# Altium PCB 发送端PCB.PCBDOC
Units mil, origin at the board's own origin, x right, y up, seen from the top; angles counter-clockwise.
Board outline 1459.66 x 397.67 mil, 4 copper layers (Top Layer, Mid-Layer 1, Mid-Layer 2, Bottom Layer); 48 components, 37 nets, 169 pads, 76 vias.
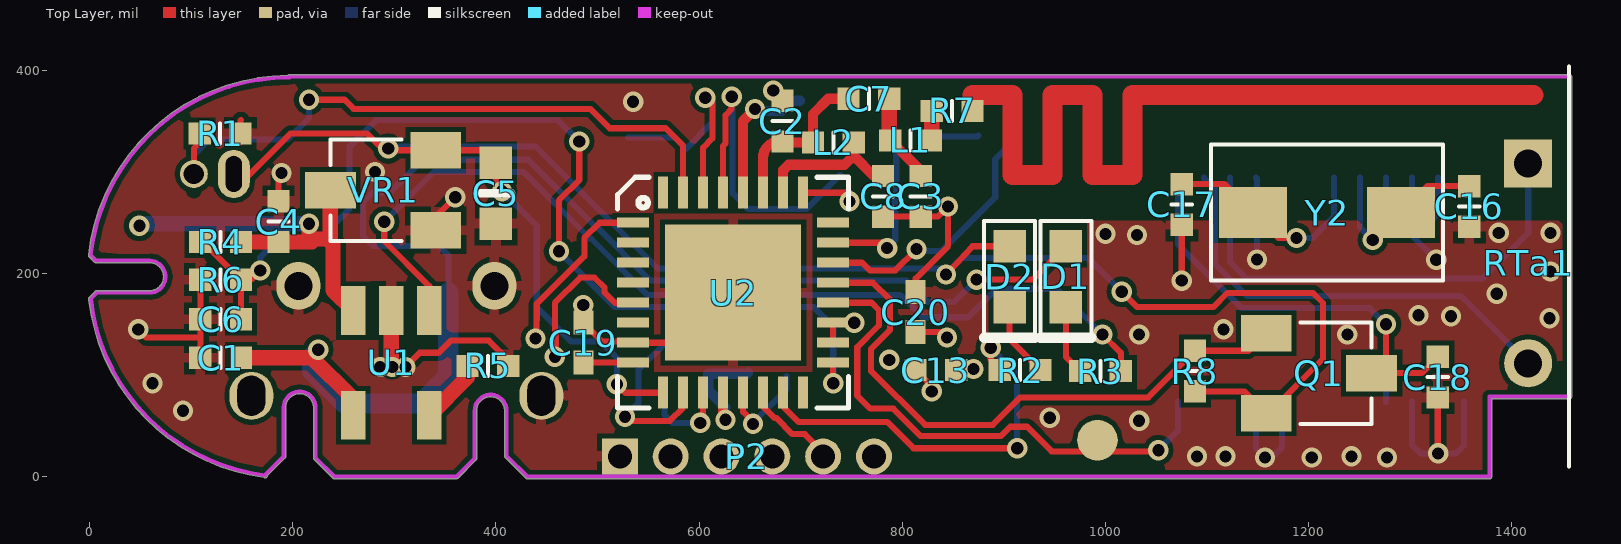
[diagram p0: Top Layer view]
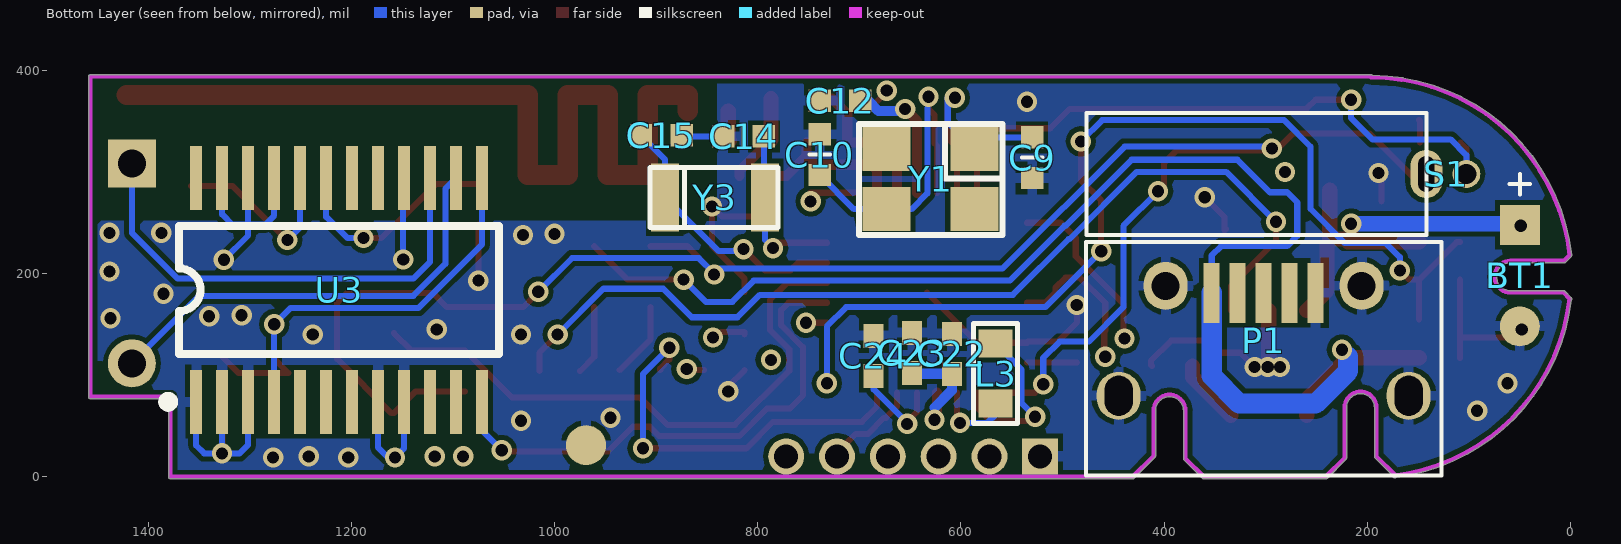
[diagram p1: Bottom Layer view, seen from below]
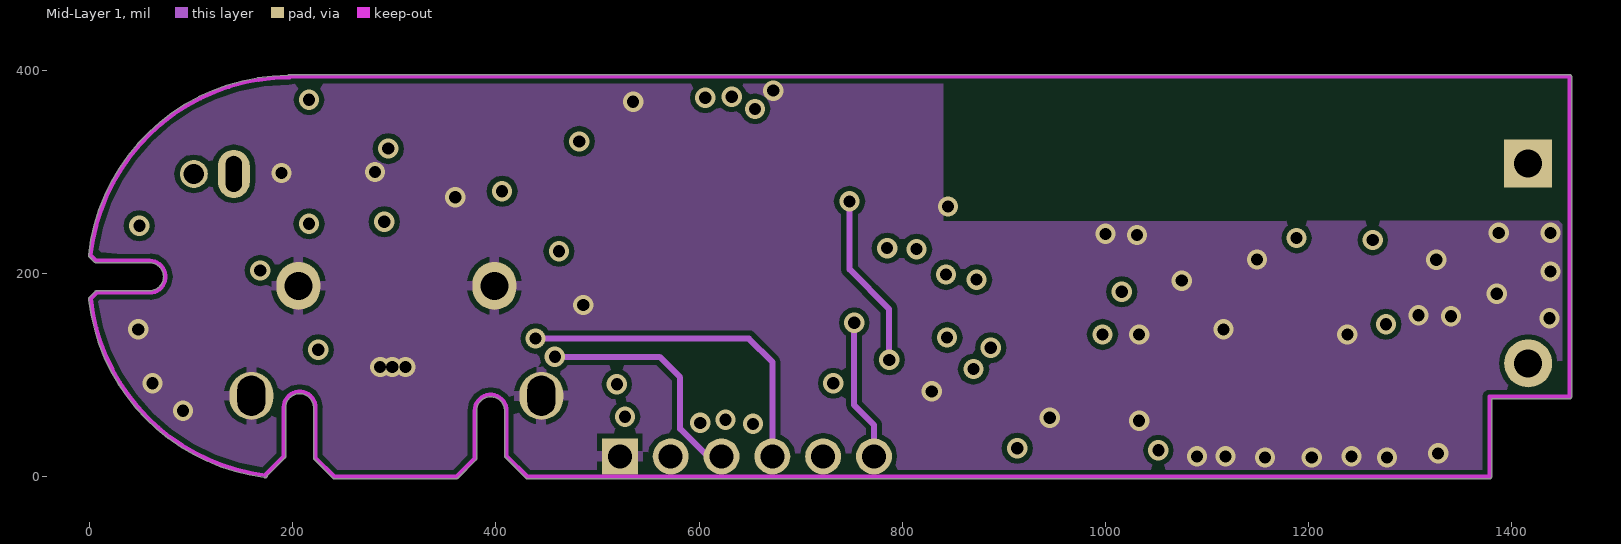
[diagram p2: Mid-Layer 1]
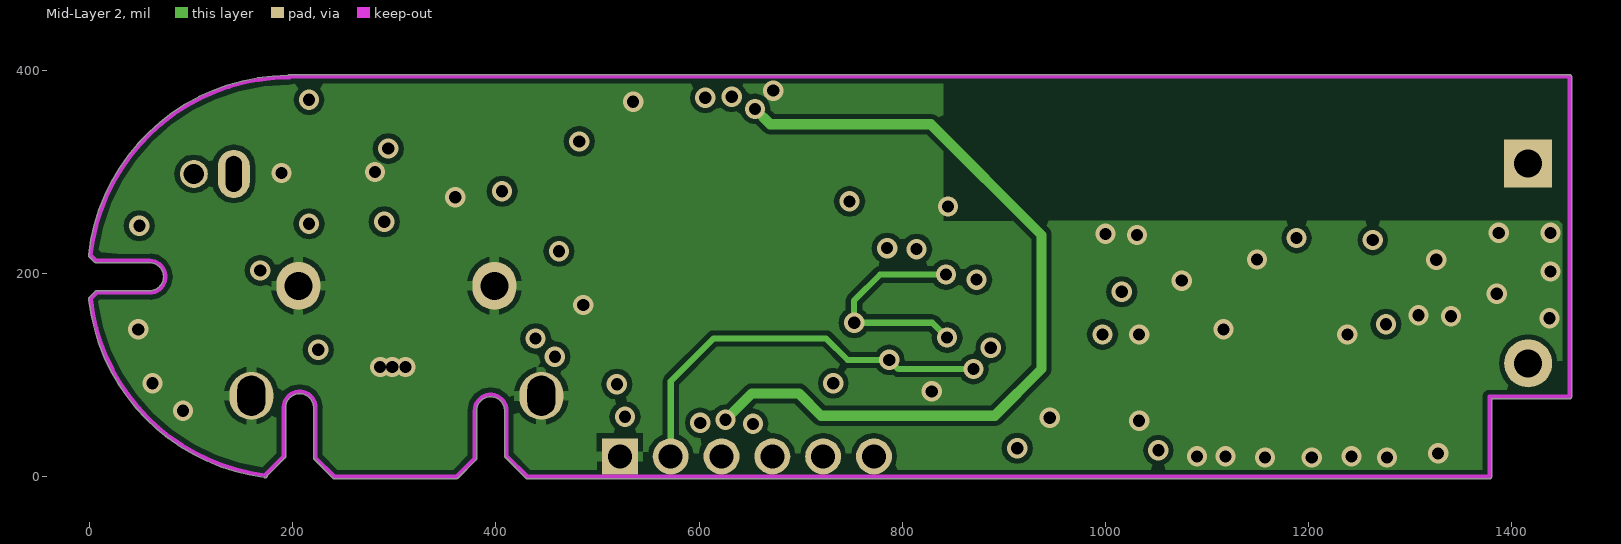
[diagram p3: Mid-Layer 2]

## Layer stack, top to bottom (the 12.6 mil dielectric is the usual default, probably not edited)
Top Layer: signal copper 1.4
Dielectric: core 12.6, FR-4, Dk 4.8
Mid-Layer 1: signal copper 1.4
Dielectric: prepreg 12.6, FR-4, Dk 4.8
Mid-Layer 2: signal copper 1.4
Dielectric: core 12.6, FR-4, Dk 4.8
Bottom Layer: signal copper 1.4

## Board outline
171.57,-0.37 ccw(c173,1) 174.98,0.98 ccw(c173.05,1.44) 175.02,1.22 192.4,18.6 192.39,18.59 ccw(c191,20) 192.98,20 192.98,68 cw(c206.75,68) 220.51,68 220.51,18.5 ccw(c222.5,18.5) 221.1,17.09 221.09,17.1 239.6,-1.4 239.59,-1.39 ccw(c241,0) 241,-1.98 361,-1.98 ccw(c361,0) 362.41,-1.39 362.4,-1.4 380.4,16.6 380.39,16.59 ccw(c379,18) 380.98,18 380.98,65 cw(c394.75,65) 408.51,65 408.51,20.5 ccw(c410.5,20.5) 409.1,19.09 409.09,19.1 429.6,-1.4 429.59,-1.39 ccw(c431,0) 431,-1.98 1377.95,-1.98 ccw(c1377.95,0) 1379.94,0 1379.94,76.76 1456.69,76.76 ccw(c1456.69,78.74) 1458.68,78.74 ccw(c1456.69,78.74) 1458.68,78.76 1458.68,393.7 ccw(c1456.69,393.7) 1456.69,395.68 196.64,395.68 ccw(c196.64,393.7) 195.14,395 ccw(c196.64,196.17) -0.97,218.22 ccw(c1,218) -0.39,216.59 -0.4,216.6 5,211.2 4.99,211.21 ccw(c6.4,212.6) 6.4,210.61 59.06,210.61 cw(c59.06,196.85) 72.82,196.85 cw(c59.06,196.85) 59.06,183.09 7.1,183.09 ccw(c7.1,181.1) 5.69,182.49 5.7,182.5 -0.4,176.4 ccw(c1,175) -0.66,173.91 ccw(c196.85,196.85)

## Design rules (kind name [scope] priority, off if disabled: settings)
Clearance [All] p1: gap=5
ComponentClearance [All] p1: gap=6 collisioncheckmode=3 verticalgap=10 showdistances=FALSE
FabricationTestpoint [(IsPad And (OnTopLayer Or OnBottomLayer))] p1: side=3 testpointundercomponent=TRUE minsize=40 maxsize=100 preferedsize=60 minholesize=0 maxholesize=40 preferedholesize=32 testpointgrid=1 allowsidetop=TRUE allowsidebottom=TRUE usegrid=TRUE gridtolerance=0.01
PolygonConnect PolygonConnect_1 [IsVia] p1: connectstyle=Direct reliefconductorwidth=10 reliefentries=4 polygonreliefangle="90 Angle"
PolygonConnect [All] p2: connectstyle=Relief reliefconductorwidth=10 reliefentries=4 polygonreliefangle="90 Angle"
RoutingCorners [All] p1: cornerstyle=Round minsetback=50 maxsetback=50
RoutingVias [All] p1: holewidth=12 width=20 viastyle="Through Hole" minholewidth=12 minwidth=20 maxholewidth=12 maxwidth=20
SilkscreenOverComponentPads SilkToSolderMaskClearance [IsPad] p1: minsilkscreentomaskgap=10
SolderMaskExpansion [All] p1: expansion=4
Width [All] p1: maxlimit=20 minlimit=6 preferedwidth=6
24 further rules are at their usual default settings.

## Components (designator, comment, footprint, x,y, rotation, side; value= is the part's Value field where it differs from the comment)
BT1 "Battery" BT 50,248 r270 bottom
C1 "1uF" 0402#1 109,117 r0 top
C2 "1.2pF/10V" 0402#1 682,330 r90 top
C3 "1.8pF/10V" 0402#1 818,256 r90 top
C4 "1uF" 0402#1 186,231 r90 top
C5 "22uF" 0603 400,309 r270 top
C6 "100nF" 0402#1 109,155 r0 top
C7 "220pF/10V" 0402#1 787,372 r180 top
C8 "18pF/10V" 0402#1 781,256 r90 top
C9 "12pF" 0402#1 530,334 r270 bottom
C10 "12pF" 0402#1 739,297 r90 bottom
C12 "2.2uF/10V" 0402#1 739,370 r180 bottom
C13 "1uF/10V" 0402#1 813,105 r0 top
C14 "6pF" 0402#1 834,335 r180 bottom
C15 "6pF" 0402#1 875,336 r0 bottom
C16 "15pF" 0402#1 1358,286 r270 top
C17 "15pF" 0402#1 1075,288 r270 top
C18 "100nF" 0402#1 1327,78 r90 top
C19 "1uF/10V" 0402#2 486,132 r270 top
C20 "0.1uF/10V" 0402#2 813,162 r270 top
C22 "1uF/10V" 0402#2 609,121 r270 bottom
C23 "0.1uF/10V" 0402#2 648,122 r270 bottom
C24 "1uF/10V" 0402#2 686,119 r270 bottom
D1 "LEDR" LED0603 961,196.85 r270 top
D2 "LEDG" LED0603 905.51,196.85 r270 top
L1 "1.8nH" 0402#1 828,331 r180 top
L2 "1.3nH" 0402#1 752,329 r180 top
L3 "47uH" 0603R 566,131 r270 bottom
P1 "microUSB" MICROUSB 302,181 r0 bottom
P2 "Header 6" SIP6-1.27 522,20 r0 top
Q1 "AO3401A" AO3401 1210,102 r270 top
R1 "10K" 0402#1 148.39,337.82 r180 top
R2 "1K" 0402#1 896,105 r0 top
R3 "1K" 0402#1 1015,104 r180 top
R4 "2M" 0402#1 109,231 r0 top
R5 "2K" 0402#1 412,109 r180 top
R6 "200K" 0402#1 109,194 r0 top
R7 "0" 0402#1 869,360 r180 top
R8 "10K" 0402#1 1088,124 r270 top
RTa1 "TX-40K" US-10mm 1416,210 r0 top
S1 "弹簧振动开关" SW 142,298 r0 bottom
U1 "TP4054" TP4054 297,112 r180 top
U2 "TLSR8258F512ET32" QFN-32 535,250 r0 top
U3 "CS102" TSSOP24 1212,184 r0 bottom
VR1 "MCP33" MCP33 237,282 r90 top
Y1 "24M" XTAL4TN_3225 630,293 r0 bottom
Y2 "8M" 5032 1218,260 r180 top
Y3 "32.768K" XTAL3215 793,275 r0 bottom

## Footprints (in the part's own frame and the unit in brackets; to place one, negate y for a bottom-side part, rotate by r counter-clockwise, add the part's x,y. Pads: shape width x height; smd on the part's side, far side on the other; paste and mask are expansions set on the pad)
0402#1 [mil]
  rect 22x22 smd: 1(0,0) 2(40,0)
  silkscreen extent 20,-10 20,10
0402#2 [mil] "Chip Capacitor, Body 1.0x0.5mm, IPC High Density"
  rect 23.62x19.68 smd: 1(-19.68,0) 2(19.69,0)
  body extent -22,-12 22,12, height 51
0603 [mil]
  rect 32x32 smd: 1(0,0) 2(60,0)
  silkscreen extent 30,-15 30,15
0603R [mm]
  rect 0.7x0.85 smd: 1(0,0) 2(1.5,0)
  silkscreen extent -0.5,-0.55 2,0.55
5032 [mm]
  rect 1.7x1.27 smd: 1(-1.85,0) 2(1.85,0)
  silkscreen extent -2.9,-1.7 2.9,1.7
AO3401 [mm]
  rect 0.915x1.27 smd: 1(-1,-1.318) 2(1,-1.318) 3(0,1.318)
  silkscreen extent -1.27,-0.46 1.27,1.32
BT [mm]
  rect 1x1 smd: 1(0,0)
  round 1 smd: 2(2.54,0)
  silkscreen extent -1.27,-0.25 -0.76,0.25
LED0603 [mil]
  rect 32x32 smd: 1(-30,0) 2(30,0)
  silkscreen extent -55,-25 60,25
MCP33 [mm]
  rect 0.915x1.27 smd: 1(0,0) 2(-1,-2.635) 3(1,-2.635)
  silkscreen extent -1.27,-1.78 1.27,0
MICROUSB [mm]
  rect 0.4x1.5 smd: 1(-1.3,0) 2(-0.65,0) 3(0,0) 4(0.65,0) 5(1.3,0)
  oval 1.1x1.2 hole 0.7 slot 1 at 90 deg: ""(-3.625,2.575) ""(3.625,2.575)
  oval 1.1x1.2 hole 0.7: ""(-2.45,-0.175) ""(2.45,-0.175)
  silkscreen extent -4.44,-1.27 4.44,4.57
QFN-32 [mm]
  rect 0.8x0.25 smd: 1(0,0) 2(0,-0.5) 3(0,-1) 4(0,-1.5) 5(0,-2) 6(0,-2.5) 7(0,-3) 8(0,-3.5) 17(5,-3.5) 18(5,-3) 19(5,-2.5) 20(5,-2) 21(5,-1.5) 22(5,-1) 23(5,-0.5) 24(5,0)
  rect 0.25x0.8 smd: 9(0.75,-4.25) 10(1.25,-4.25) 11(1.75,-4.25) 12(2.25,-4.25) 13(2.75,-4.25) 14(3.25,-4.25) 15(3.75,-4.25) 16(4.25,-4.25) 25(4.25,0.75) 26(3.75,0.75) 27(3.25,0.75) 28(2.75,0.75) 29(2.25,0.75) 30(1.75,0.75) 31(1.25,0.75) 32(0.75,0.75)
  rect 3.4x3.4 smd: 33(2.5,-1.75)
  silkscreen extent -0.39,-4.64 5.39,1.14
SIP6-1.27 [mm]
  rect 0.9x0.9 hole 0.6: 1(0,0)
  round 0.9 hole 0.6: 2(1.27,0) 3(2.54,0) 4(3.81,0) 5(5.08,0) 6(6.35,0)
SW [mm]
  oval 0.8x1.2 hole 0.4 slot 0.9 at 90 deg: 1(0,0)
  round 0.7 hole 0.508: 2(-1,0)
  silkscreen extent 0,-1.52 8.5,1.52
TP4054 [mm]
  rect 0.62x1.22 smd: 1(-0.95,-1.31) 2(0,-1.31) 3(0.95,-1.31) 4(0.95,1.31) 5(-0.95,1.31)
TSSOP24 [mm] "Shrink Small Outline; 24 Leads; Body Width 4.4 mm; Pitch 0.65 mm"
  rect 0.3x1.6 smd: 1(3.575,2.8) 2(2.925,2.8) 3(2.275,2.8) 4(1.625,2.8) 5(0.975,2.8) 6(0.325,2.8) 7(-0.325,2.8) 8(-0.975,2.8) 9(-1.625,2.8) 10(-2.275,2.8) 11(-2.925,2.8) 12(-3.575,2.8) 13(-3.575,-2.8) 14(-2.925,-2.8) 15(-2.275,-2.8) 16(-1.625,-2.8) 17(-0.975,-2.8) 18(-0.325,-2.8) 19(0.325,-2.8) 20(0.975,-2.8) 21(1.625,-2.8) 22(2.275,-2.8) 23(2.925,-2.8) 24(3.575,-2.8)
  silkscreen extent -4,-1.6 4.4,2.92
US-10mm [mm]
  round 1.2 hole 0.7: +(0,-2.5)
  rect 1.2x1.2 hole 0.7: -(0,2.5)
  silkscreen extent 1.02,-5.08 1.02,4.92
XTAL4TN_3225 [mm]
  rect 1.2x1.1 smd: 1(-1.1,-0.75) 2(1.1,0.75) 3(1.1,-0.75) 4(-1.1,0.75)
  silkscreen extent -1.8,-1.38 1.79,1.4
XTAL3215 [mm]
  rect 0.7x1.7 smd: 1(2.5,0) 2(0,0)
  silkscreen extent -0.33,-0.75 2.87,0.75

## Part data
BT1: "Multicell Battery"
C1 C2 C3 C4 C5 C6 C7 C8 C9 C10 C12 C13 C14 C15 C16 C17 C18 C19 C20 C22 C23 C24: library part Cap, "Capacitor"
D1 D2: library part LED0, "Typical INFRARED GaAs LED"
L1 L2 L3: library part Inductor, "Inductor"
P1: library part "Header 5", "Header, 5-Pin"
P2: "Header, 6-Pin"
Q1: library part "AO3401A P道沟 X13A15 SOT-23", "MOS(场效应管)"
R1 R2 R3 R4 R5 R6 R7 R8: library part Res1, "Resistor"
RTa1: library part TC40K
S1: library part SW-SPST, "Single-Pole, Single-Throw Switch"
U3: library part CS100
VR1: library part "Volt Reg", "Voltage Regulator"
Y1 Y2 Y3: library part XTAL, "Crystal Oscillator"

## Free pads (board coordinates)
  round 40 smd: 0(992,36)
  round 39.37 smd far side: 1(969,31)

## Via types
v1: diameter 20, hole 12, Top Layer to Bottom Layer, tented both sides, 76 vias

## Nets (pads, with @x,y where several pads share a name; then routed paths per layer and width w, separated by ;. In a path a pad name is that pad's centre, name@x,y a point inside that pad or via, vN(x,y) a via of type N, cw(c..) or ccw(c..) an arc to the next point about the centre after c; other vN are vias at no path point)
1.2V: C12.2 C22.2 C23.2 U2.12 U2.28 | length 1055.5
  Top Layer w10: v1@623.58,58.58 U2.12 ; U2.28 643.27,350.27 v1(655,362)
  Mid-Layer 2 w10: v1(626,56) 652,82 698,82 720,60 891,60 937,106 937,238 828,347 670,347 v1(655,362)
  Bottom Layer w10: 626,68 609,85 C22.2 647,101.31 C23.2 ; v1(655,362) 657,360 681.28,360 691.28,370 C12.2
+3.3V: C5.1 C20.2 D2.1 P2.6 Q1.2 R8.2 S1.1 U2.9 U2.18 U2.19 VR1.3 | length 2358.4
  Top Layer w6: S1.1@142,282 198,338 273,338 288,323 v1(294,323) ; v1@294,321.37 VR1.3 387.63,321.37 C5.1 400,287 v1(406,281) ; v1(519,91) 527.32,82.68 U2.9 ; U2.18 U2.19 v1(752.57,151.57) ; C20.2@813,140.13 C20.2 838.69,142.31 v1(844,137) ; v1(843,199) 869.15,226.85 D2.1 ; v1(1016,182) 1031,167 1106,167 1120,181 1204,181 1214,171 1214,116 1160.63,62.63 Q1.2 1136.76,84 R8.2
  Mid-Layer 1 w6: v1(752.57,151.57) 752.57,70.43 772,51 P2.6
  Mid-Layer 2 w6: v1(843,199) 778,199 752.57,173.57 v1(752.57,151.57) 829.43,151.57 v1(844,137)
  Bottom Layer w6: v1(294,323) 296,325 439,325 559,205 837,205 v1(843,199) 843,200.04 858.11,215.15 982.85,215.15 v1(1016,182) ; v1(406,281) 440.1,246.9 440.1,166.9 474,133 503,133 519,117 v1(519,91)
+5V: C1.2 D1.1 P1.5 U1.4 | length 1388.2
  Top Layer w6: v1(873,194) 928.15,194 D1.1
  Top Layer w15: C1.2 217,117 ; v1@218,118 259.6,76.4 U1.4
  Bottom Layer w6: 347.03,312 377,312 ; P1.5 353.18,217.82 344,227 279,227 269,237 269,270 279,280 296,280 328,312 377,312 ; 497,247 432,312 377,312 ; 498,247 552,193 804,193 825,172 851,172 v1(873,194)
  Bottom Layer w15: v1@218,118 v1(225,125)
  Bottom Layer w20: v1@219,118 219,104 251,72 326,72 353.18,99.18 P1.5
ADC0: C6.2 R4.1 R6.2 U2.17 | length 1037.7
  Top Layer w6: R4.1 112,231 R6.2 ; C6.2 R6.2 ; v1(168,203) 159,194 R6.2 ; v1(462,222) 462,272 482,292 v1(482,330) ; v1@731.85,92.15 U2.17
  Bottom Layer w6: v1(168,203) 168,216 182,230 222.46,230 256,263.54 256,325 282,351 461,351 v1(482,330) ; v1(462,222) 517,167 713,167 732,148 v1(732,92)
CS102-EN: Q1.1 R8.1 U2.21 | length 589.6
  Top Layer w6: U2.21 771.05,190.95 788,174 788,144.46 769,125.46 769,104 769.56,104 822.56,51 889,51 916,78 1042,78 R8.1 1140.76,124 Q1.1
CS102-T: pad.0 U2.20 U3.12 | length 524
  Top Layer w6: U2.20 769.74,171.26 777,164 777,149.01 755.6,127.61 755.6,79.85 768.44,67 791,67 818,40 897,40 906.16,49.16 922.84,49.16 947,25 1051,25 v1(1052,26)
  Bottom Layer w6: v1(1052,26) 1071.25,45.25 U3.12
GND: BT1.2 C1.1 C2.2 C3.1 C4.2 C5.2 C6.1 C8.1 C9.2 C10.2 C12.1 C13.1 C14.1 C15.1 C16.2 C17.2 C18.1 C19.1 C20.1 C22.1 C23.1 C24.1 P1. P1.1 P2.1 pad.1 R1.1 R5.1 R6.1 U1.2 U2.7 U2.33 U3.1 U3.2 U3.3 U3.8 U3.9 U3.16 U3.21 U3.22 U3.23 VR1.2 | length 1597.5
  Top Layer w6: v1(48,145) 56,137 109,137 ; C1.1 109,137 ; R6.1 C6.1 109,137 ; R1.1@148.39,328.82 148.39,350.39 149,351 ; C4.2 186,296 v1(189,299) ; v1(311,108) 325,122 343.61,122 355.61,134 393,134 413,114 413,110 R5.1 ; VR1.2@339.37,244 VR1.2 340.74,255.74 v1(360,275) ; v1(486,169) C19.1 504.69,133 533.89,133 U2.7 584.21,131.89 U2.33 ; v1@668.27,383.73 C2.2 ; C8.1 C3.1 835,256 v1(845,266) 845,227 813,195 C20.1 ; C13.1 829,89 v1(829,84) ; v1(1075,193) C17.2 ; C18.1 1327,23.31 v1(1327.31,23)
  Top Layer w15: U1.2 297,109 v1(298,108)
  Bottom Layer w6: C14.1 874,335 C15.1 ; U3.9 1148.02,27.98 v1(1157,19) 1164,19 1173.61,28.61 U3.8 ; U3.16 1149,293.26 v1(1149,213.82) ; U3.21 1275.98,257.02 1285,248 1317,248 1327.16,258.16 U3.23 ; U3.3 1301.57,31.43 1310,23 v1(1327.31,23) ; U3.22 1301.57,237.43 v1(1325.49,213.51) ; U3.2 1327.16,23.16 v1(1327.31,23) ; U3.1 1352.75,30.75 1345,23 v1(1327.31,23)
  other v1: 1203,19 1277,19 1090,20 1118,20 1242,20 1033,55 945,58 92,65 62,92 286,108 1033,140 1238,140 1116,145 1437,156 1340,158 1308,159 1385,180 1438,202 1031,238 1000,239 1387,240 1438,240 281,300 535,369 673,380
LED: R2.1 U2.15 | length 396.5
  Top Layer w6: U2.15 682.64,68.97 697.6,54 785,54 811,28 v1(913,28) ; v1(887,127) 887,115.46 896,106.46 R2.1
  Bottom Layer w6: v1(887,127) 913,101 v1(913,28)
NetC2_1: C2.1 C7.2 L2.2 U2.27 | length 162.3
  Top Layer w10: U2.27 662.95,313.95 cw(c679,313.95) 679,330 680,329 L2.2 712,357 727,372 C7.2
NetC3_2: C3.2 C7.1 L1.2 | length 88.8
  Top Layer w10: L1.2 818,301 C3.2
  Top Layer w15: C7.1 787,332 L1.2
NetC8_2: C8.2 L2.1 U2.26 | length 147.7
  Top Layer w10: U2.26 682.64,301.64 688,307 743,307 752,316 ; L2.1 752,316 ; C8.2 772,296 752,316
NetC9_1: C9.1 U2.30 Y1.1 | length 217.8
  Top Layer w6: U2.30 603.9,323.9 613,333 613,373 v1(606,373)
  Bottom Layer w6: C9.1 Y1.1@575.22,334 ; Y1.1 613,348.83 613,373 v1(606,373)
NetC10_1: C10.1 U2.29 Y1.2 | length 308.3
  Top Layer w6: U2.29 623.58,325.58 626,328 626,356 632,362 v1(632,374)
  Bottom Layer w6: 633,363 633,279 648.53,263.47 Y1.2 705.47,263.47 C10.1
NetC14_2: C14.2 U2.23 Y3.2 | length 156.4
  Top Layer w6: U2.23 779.68,230.32 v1(785,225)
  Bottom Layer w6: 793,233 Y3.2 ; Y3.2@794,276 C14.2
NetC15_2: C15.2 U2.22 Y3.1 | length 266.2
  Top Layer w6: U2.22 760.37,210.63 768,203 793,203 v1(814,224)
  Bottom Layer w6: v1(814,224) 814,222 838.43,222 Y3.1 891.43,312.43 C15.2
NetC16_1: C16.1 U3.20 Y2.1 | length 183.4
  Top Layer w6: v1(1263,233) 1263.83,233 Y2.1 1316.83,286 C16.1
  Bottom Layer w6: U3.20 1250.39,245.61 v1(1263,233)
NetC17_1: C17.1 U3.19 Y2.2 | length 218.8
  Top Layer w6: C17.1 1117.17,288 Y2.2 1170.17,235 v1(1188,235)
  Bottom Layer w6: v1(1188,235) 1204,235 1224.8,255.8 U3.19
NetC19_2: C19.2 U2.8 | length 48.9
  Top Layer w6: C19.2 U2.8@534.89,112.31
NetC24_2: C24.2 U2.13 | length 113.4
  Top Layer w6: U2.13 643.27,63.73 v1@651,56 ; v1@649.58,52.75 649.58,54.58 v1@651,56 ; v1@656,51 651,51 v1@651,56
  Bottom Layer w6: v1@649.58,52.75 649.58,54.58 651,54.58 651,51 686,86 C24.2
  other v1: 653,52
NetD1_2: D1.2 R3.2 | length 68.6
  Top Layer w6: D1.2 961,118 R3.2
NetD2_2: D2.2 R2.2 | length 74.5
  Top Layer w6: D2.2 905.51,135.49 R2.2
NetL1_1: L1.1 R7.2 | length 29.4
  Top Layer w15: L1.1 829,332 R7.2
NetL3_1: L3.1 U2.10 | length 167
  Top Layer w6: v1(527,59) 531,55 571.13,55 584.21,68.08 U2.10
  Bottom Layer w6: v1(527,59) 540.27,72.27 540.27,105.27 L3.1
NetL3_2: L3.2 U2.11 | length 85.9
  Top Layer w6: v1@598.58,55.16 v1@598.58,55.58 ; U2.11 603.9,60.9 v1@598.58,55.58 ; v1@598.58,55.58 598,55 598,56.42 598.58,56.42 v1@598.58,55.58
  Bottom Layer w6: L3.2 566,61 574,53 v1(601,53) ; v1@598,55 598,56.42 598.58,56.42 v1@598.58,55.16
NetR3_1: R3.1 U1.1 | length 966
  Top Layer w6: v1(290,251) 290,232 334.4,187.6 U1.1 ; v1(997,140) 1015,122 R3.1
  Bottom Layer w6: v1(290,251) 339,300 427.03,300 493.03,234 494.03,234 549.03,179 798,179 820,157 865,157 893,185 952,185 v1(997,140)
NetR5_2: R5.2 U1.5 | length 64.1
  Top Layer w15: U1.5 372,98.02 R5.2
RESET: C13.2 P2.2 U2.25 | length 636.7
  Top Layer w6: U2.25 v1@748,279.53 ; C13.2 v1@870,105
  Mid-Layer 1 w6: v1(748,271) 748,204 787,165 v1(787,115)
  Mid-Layer 2 w6: P2.2 572,94 614,136 725,136 746,115 v1(787,115) 796,106 v1(870,106)
RX: U2.3
S_TN: RTa1.- U3.15 | length 470.2
  Bottom Layer w6: U3.15 1122.43,211.57 1139,195 1371,195 1416,240 RTa1.-
S_TP: RTa1.+ U3.14 | length 438.2
  Bottom Layer w6: U3.14 1107.53,283.55 1107.53,209.5 1139.03,178 1349.57,178 RTa1.+
SWM: P2.4 U2.1 | length 510.6
  Top Layer w6: v1(439,136) 440,135 440,154.39 440.1,154.5 440.1,170.1 487,217 487,235 502,250 U2.1
  Mid-Layer 1 w6: v1(439,136) 649,136 672,113 P2.4
SWS: P2.3 U2.5 | length 388.5
  Top Layer w6: v1(458,118) 458,126.13 459,127.13 459,142.87 458,143.87 458,171.03 482.97,196 497,196 507,186 507,181.26 517,171.26 U2.5
  Mid-Layer 1 w6: v1(458,118) 561,118 581.18,97.82 581.18,47.18 608.37,20 P2.3
TP: P2.5 U2.14 | length 91.4
  Top Layer w6: U2.14 662.95,68.96 673.99,57.93 675.85,57.93 691.78,42 704,42 P2.5@722,24
TX: U2.6
VBAT: BT1.1 C4.1 R4.2 U1.3 VR1.1 | length 404.3
  Top Layer w15: R4.2 C4.1 219,231 216,234 ; v1(216,249) 216,234 ; 237,231 239.7,228.3 239.7,183.48 U1.3 ; VR1.1 237,232 235,234 216,234
  Bottom Layer w15: BT1.1 51,249 v1(216,249)
  other v1: 49,247
VCC-CS102: C18.2 Q1.3 U3.4 U3.13 | length 504.7
  Top Layer w6: v1(1275.98,150.02) 1275.98,116.11 Q1.3 1311,102 C18.2
  Bottom Layer w6: U3.13 1071.25,228.81 1134.06,166 1260,166 v1(1275.98,150.02) U3.4
WKUP: R1.2 S1.2 U2.31 | length 652.4
  Top Layer w6: S1.2 102.63,323.06 R1.2@108.39,328.82 ; v1(216,371) 251,371 260,362 432,362 ; 452.97,362 432,362 ; U2.31 584.21,325.79 567,343 512,343 493,362 432,362
  Bottom Layer w6: S1.2 102.63,316.63 118,332 195,332 216,353 v1(216,371)
pads on no net: P1.2 P1.3 P1.4 R7.1 U2.2 U2.4 U2.16 U2.24 U2.32 U3.5 U3.6 U3.7 U3.10 U3.11 U3.17 U3.18 U3.24 Y1.3 Y1.4
copper on no net: | length 882.6
  Top Layer w20: 869,360 869,375.73 908.39,375.73 908.39,297.01 947.77,297.01 947.77,375.73 987.16,375.73 987.16,297.01 1026.54,297.01 1026.54,375.73 1421,375.73

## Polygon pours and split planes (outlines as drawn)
GND on Top Layer "Top Layer-No Net" (solid, remove dead copper, pour order 1000): 21,452 54,485 1504,485 1504,-8 1513,-17 1432,-98 727,-98 141,-98 30,13 -21,64 -21,216 -21,418 27,466
GND on Mid-Layer 1 "Top Layer-No Net" (solid, remove dead copper, pour order 1001): 21,452 54,485 1504,485 1504,-8 1513,-17 1432,-98 727,-98 141,-98 30,13 -21,64 -21,216 -21,418 27,466
GND on Mid-Layer 2 "Top Layer-No Net" (solid, remove dead copper, pour order 1002): 21,452 54,485 1504,485 1504,-8 1513,-17 1432,-98 727,-98 141,-98 30,13 -21,64 -21,216 -21,418 27,466
GND on Bottom Layer "Top Layer-No Net" (solid, remove dead copper, pour order 1003): 21,452 54,485 1504,485 1504,-8 1513,-17 1432,-98 727,-98 141,-98 30,13 -21,64 -21,216 -21,418 27,466

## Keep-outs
Keep-Out Layer:
  lines w3.94: 1,175 7.1,181.1 59.06,181.1 ccw(c59.06,196.85) 59.06,212.6 6.4,212.6 1,218 cw(c196.64,196.17) 196.64,393.02 ; 1.21,175.02 ccw(c196.85,196.85) 173.05,1.44 ; 173,1 173,2 191,20 191,68 cw(c206.75,68) 222.5,68 222.5,18.5 241,0 361,0 379,18 379,65 cw(c394.75,65) 410.5,65 410.5,20.5 ; 196.64,393.7 1456.69,393.7 1456.69,78.74 1377.95,78.74 1377.95,0 431.89,0 431,0 411,20 ; 410.5,20.5 411,20 ; 410.5,20.5 411,20

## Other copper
Multi-Layer:
  pour cut-out: 825,395 840,393.7 840,320 840,251.69 1453,252 1455,250 1456.69,251.69 1456.69,393.7 824,393.7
